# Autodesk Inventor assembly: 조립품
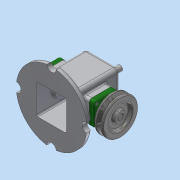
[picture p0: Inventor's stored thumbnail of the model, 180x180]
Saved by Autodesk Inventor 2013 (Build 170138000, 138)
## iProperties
Created: 2018-07
Part Number: 조립품
Document SubType Name: Assembly
Designer: Administrator
Author: Administrator
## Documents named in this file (16)
- C:\Users\Administrator\Desktop\480708V1004\조립품.iam
- C:\Users\Administrator\Desktop\480708V1004\본체.ipt
- C:\Users\Administrator\Desktop\480708V1004\고정핀 1.2x8.ipt
- C:\Users\Administrator\Desktop\480708V1004\뒤커버.ipt
- C:\Users\Administrator\Desktop\480708V1004\링크.ipt
- C:\Users\Administrator\Desktop\480708V1004\멈춤나사 M3x8.ipt
- C:\Users\Administrator\Desktop\480708V1004\베어링 12x32x10.ipt
- C:\Users\Administrator\Desktop\480708V1004\볼트 M4.ipt
- C:\Users\Administrator\Desktop\480708V1004\부시.ipt
- C:\Users\Administrator\Desktop\480708V1004\슬라이드.ipt
- C:\Users\Administrator\Desktop\480708V1004\앞커버.ipt
- C:\Users\Administrator\Desktop\480708V1004\오일 실 12 25 7.ipt
- C:\Users\Administrator\Desktop\480708V1004\키 4x4x10.ipt
- C:\Users\Administrator\Desktop\480708V1004\편심축.ipt
- C:\Users\Administrator\Desktop\480708V1004\핀 5x18.ipt
- C:\Users\Administrator\Desktop\480708V1004\V벨트풀리.ipt
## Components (3 placed, 3 different names)
1. 고정핀 1.2x8:1
2. 핀 5x18:1
3. V벨트풀리:2 — 각도:1, 플러쉬:5
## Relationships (2: Angle 1, Flush 1)
- 각도:1 [Angle]: V벨트풀리:2
- 플러쉬:5 [Flush]: V벨트풀리:2
